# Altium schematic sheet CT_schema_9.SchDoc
size 278 x 170 mm
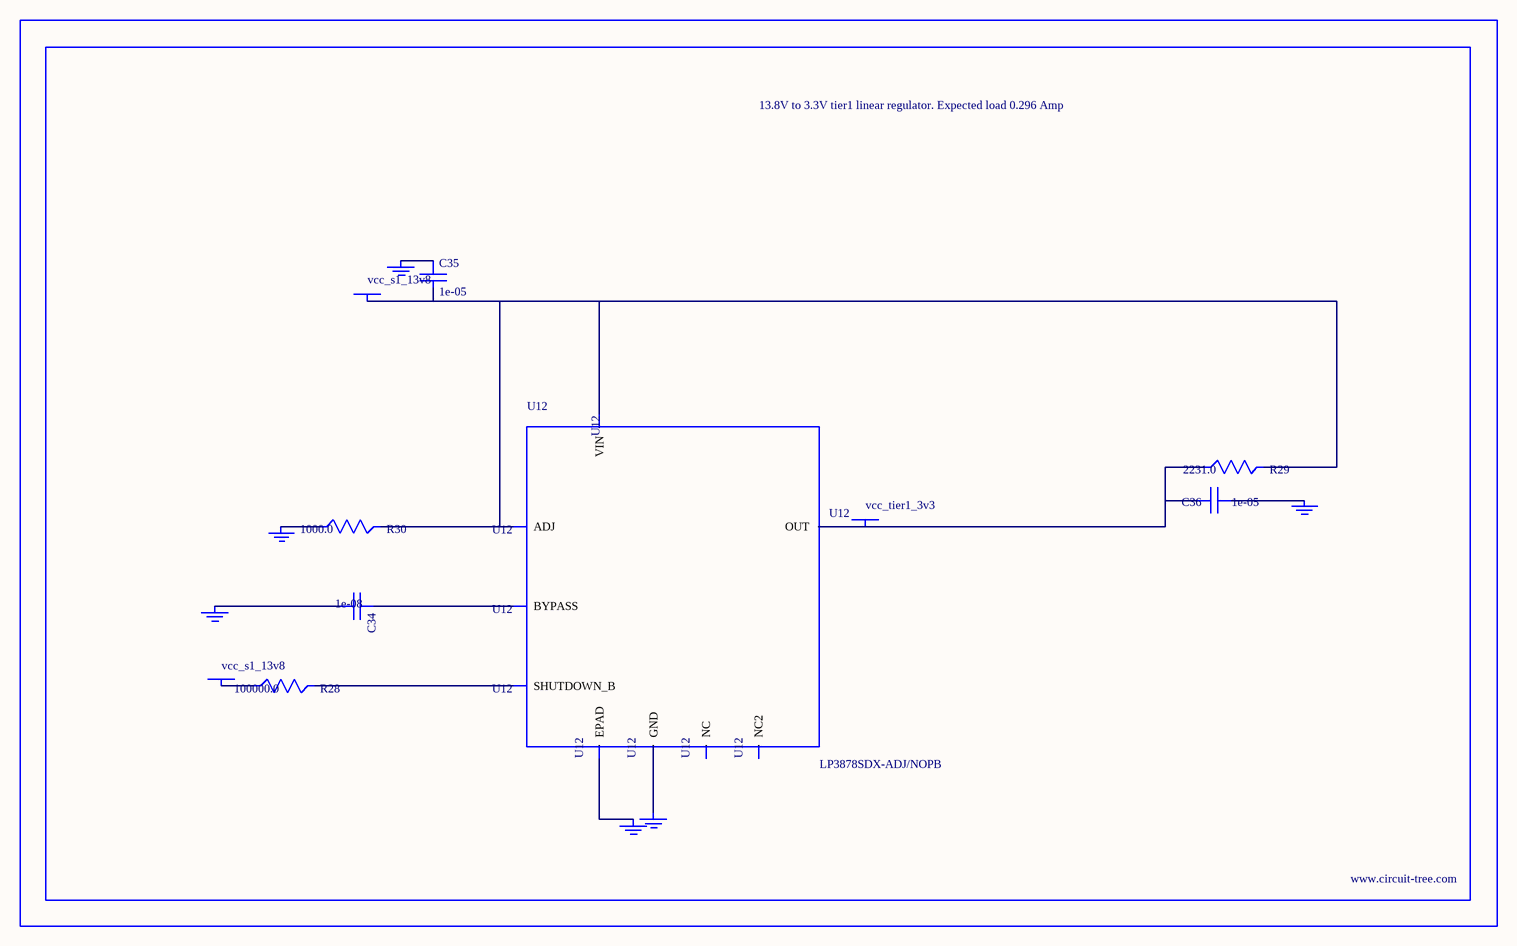
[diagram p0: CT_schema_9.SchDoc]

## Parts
BORDER8  (no value)
C34  1e-08  [C0402]
C35  1e-05  [C1210]
C36  1e-05  [C1210]
GND_INSTANCE_8_0  (no value)
GND_INSTANCE_8_1  (no value)
GND_INSTANCE_8_2  (no value)
GND_INSTANCE_8_3  (no value)
GND_INSTANCE_8_4  (no value)
GND_INSTANCE_8_5  (no value)
POWER_INSTANCE_8_0  vcc_s1_13v8
POWER_INSTANCE_8_1  vcc_s1_13v8
POWER_INSTANCE_8_2  vcc_tier1_3v3
R28  100000.0  [R0603]
R29  2231.0  [R0603]
R30  1000.0  [R0603]
U12  LP3878SDX-ADJ/NOPB  [WSON-8]

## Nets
NetC34_1: C34.1 U12.1(BYPASS)
NetC34_2: C34.2 GND_INSTANCE_8_0.0(GND)
NetC35_1: C35.1 GND_INSTANCE_8_1.0(GND)
NetC35_2: C35.2 POWER_INSTANCE_8_0.0(PWR) R29.2 R30.2 U12.4(VIN) U12.6(ADJ)
NetC36_1: C36.1 GND_INSTANCE_8_2.0(GND)
NetC36_2: C36.2 POWER_INSTANCE_8_2.0(PWR) R29.1 U12.5(OUT)
NetGND_INSTANCE_8_3_0: GND_INSTANCE_8_3.0(GND) R30.1
NetGND_INSTANCE_8_4_0: GND_INSTANCE_8_4.0(GND) U12.PAD(EPAD)
NetGND_INSTANCE_8_5_0: GND_INSTANCE_8_5.0(GND) U12.3(GND)
NetPOWER_INSTANCE_8_1_0: POWER_INSTANCE_8_1.0(PWR) R28.1
NetR28_2: R28.2 U12.8(SHUTDOWN_B)

Not connected (* = marked no-connect by the designer): U12 2(NC) 7(NC2)

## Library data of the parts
BORDER8 = BORDER_PAGE8
C34 = C0402C103K3RAC
C35 = C1210C106K5PACTU
C36 = GRM32DR61E106MA12L
GND_INSTANCE_8_0-GND_INSTANCE_8_5 = GND
POWER_INSTANCE_8_0-POWER_INSTANCE_8_2 = PWR
R28 = RC0603JR-07100KL
R29 = R29
R30 = RC0603JR-071KL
